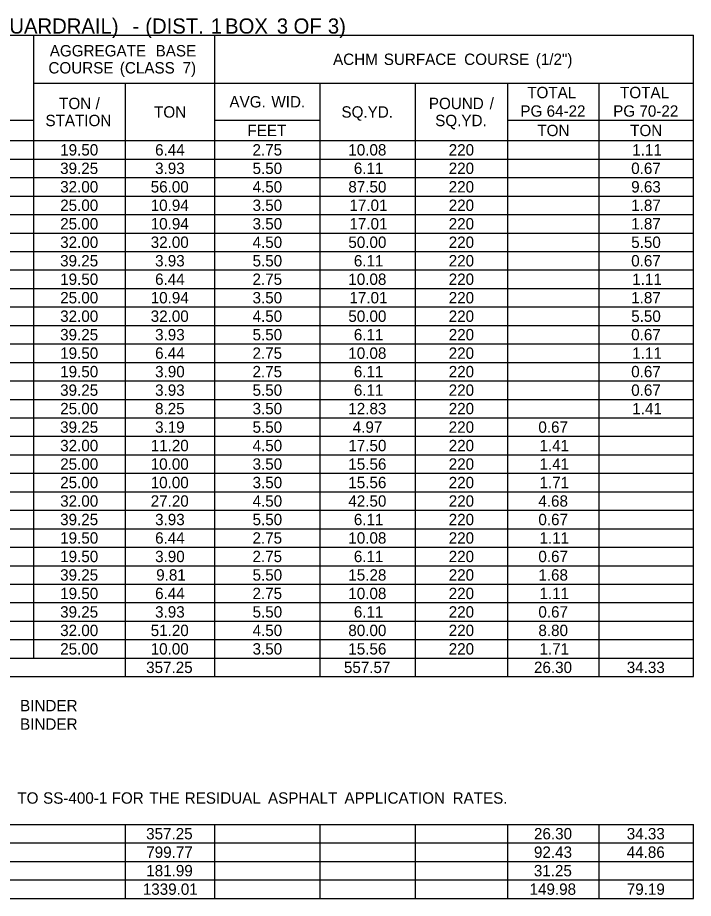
# Model space of a CAD drawing. Extents: x 542596 to 1930787, y -1948294 to 596640.
# Drawn here: x 554490.8 to 554847.5, y -1946673.7 to -1946209.1 of the extents above; entities that cross this region are included whole.
import ezdxf

# ---------------------------------------------------------------- set-up
doc = ezdxf.new("R2010")
doc.units = 0
doc.layers.add('Default', color=7, linetype='Continuous')

msp = doc.modelspace()

# ---------------------------------------------------------------- linework, layer by layer
at = {"layer": 'Default'}
for p, q in [((554098.71, -1946218.4), (554847.51, -1946218.4)), ((554499.43, -1946546.98), (554499.43, -1946218.4)), ((554594.98, -1946556.73), (554594.98, -1946218.4)), ((554847.51, -1946556.73), (554847.51, -1946218.4)), ((554499.43, -1946243.75), (554847.51, -1946243.75)), ((554547.7, -1946556.73), (554547.7, -1946243.75)), ((554650.56, -1946243.75), (554700.77, -1946243.75)), ((554650.56, -1946556.73), (554650.56, -1946243.75)), ((554700.77, -1946556.73), (554700.77, -1946243.75)), ((554749.52, -1946556.73), (554749.52, -1946243.75)), ((554797.78, -1946556.73), (554797.78, -1946243.75)), ((554452.15, -1946263.25), (554499.43, -1946263.25)), ((554499.43, -1946546.98), (554499.43, -1946263.25)), ((554594.98, -1946263.25), (554650.56, -1946263.25)), ((554594.98, -1946273.98), (554594.98, -1946263.25)), ((554650.56, -1946303.23), (554650.56, -1946263.25)), ((554749.52, -1946263.25), (554847.51, -1946263.25)), ((554098.71, -1946273.98), (554847.51, -1946273.98)), ((554499.43, -1946273.98), (554650.56, -1946273.98)), ((554547.7, -1946303.23), (554547.7, -1946273.98)), ((554650.56, -1946273.98), (554847.51, -1946273.98)), ((554700.77, -1946303.23), (554700.77, -1946273.98)), ((554329.78, -1946283.73), (554847.51, -1946283.73)), ((554329.78, -1946293.48), (554847.51, -1946293.48)), ((554329.78, -1946303.23), (554847.51, -1946303.23)), ((554329.78, -1946312.98), (554797.78, -1946312.98)), ((554547.7, -1946556.73), (554547.7, -1946312.98)), ((554650.56, -1946439.73), (554650.56, -1946312.98)), ((554749.52, -1946312.98), (554797.78, -1946312.98)), ((554797.78, -1946312.98), (554847.51, -1946312.98)), ((554329.78, -1946322.73), (554847.51, -1946322.73)), ((554329.78, -1946332.48), (554847.51, -1946332.48)), ((554329.78, -1946342.23), (554847.51, -1946342.23)), ((554329.78, -1946351.98), (554847.51, -1946351.98)), ((554700.77, -1946546.98), (554700.77, -1946351.98)), ((554329.78, -1946361.73), (554847.51, -1946361.73)), ((554329.78, -1946371.48), (554847.51, -1946371.48)), ((554329.78, -1946381.23), (554847.51, -1946381.23)), ((554329.78, -1946390.98), (554847.51, -1946390.98)), ((554329.78, -1946400.73), (554847.51, -1946400.73)), ((554329.78, -1946410.48), (554847.51, -1946410.48)), ((554329.78, -1946420.23), (554847.51, -1946420.23)), ((554329.78, -1946429.98), (554847.51, -1946429.98)), ((554329.78, -1946439.73), (554847.51, -1946439.73)), ((554329.78, -1946449.48), (554847.51, -1946449.48)), ((554650.56, -1946556.73), (554650.56, -1946449.48)), ((554329.78, -1946459.23), (554847.51, -1946459.23)), ((554329.78, -1946468.98), (554847.51, -1946468.98)), ((554329.78, -1946478.73), (554847.51, -1946478.73)), ((554270.31, -1946488.48), (554847.51, -1946488.48)), ((554329.78, -1946498.23), (554847.51, -1946498.23)), ((554329.78, -1946507.98), (554847.51, -1946507.98)), ((554329.78, -1946517.73), (554847.51, -1946517.73)), ((554329.78, -1946527.48), (554847.51, -1946527.48)), ((554329.78, -1946537.23), (554847.51, -1946537.23)), ((554098.71, -1946546.98), (554847.51, -1946546.98)), ((554547.7, -1946546.98), (554594.98, -1946546.98)), ((554594.98, -1946546.98), (554650.56, -1946546.98)), ((554594.98, -1946556.73), (554594.98, -1946546.98)), ((554650.56, -1946546.98), (554700.77, -1946546.98)), ((554700.77, -1946546.98), (554847.51, -1946546.98)), ((554749.52, -1946556.73), (554749.52, -1946546.98)), ((554329.78, -1946556.73), (554847.51, -1946556.73)), ((554329.78, -1946634.73), (554847.51, -1946634.73)), ((554329.78, -1946634.73), (554847.51, -1946634.73)), ((554547.7, -1946673.73), (554547.7, -1946634.73)), ((554594.98, -1946673.73), (554594.98, -1946634.73)), ((554594.98, -1946673.73), (554594.98, -1946634.73)), ((554650.56, -1946673.73), (554650.56, -1946634.73)), ((554650.56, -1946673.73), (554650.56, -1946634.73)), ((554700.77, -1946673.73), (554700.77, -1946634.73)), ((554700.77, -1946673.73), (554700.77, -1946634.73)), ((554749.52, -1946673.73), (554749.52, -1946634.73)), ((554749.52, -1946673.73), (554749.52, -1946634.73)), ((554797.78, -1946673.73), (554797.78, -1946634.73)), ((554847.51, -1946673.73), (554847.51, -1946634.73)), ((554329.78, -1946644.48), (554847.51, -1946644.48)), ((554329.78, -1946654.23), (554847.51, -1946654.23)), ((554329.78, -1946663.98), (554847.51, -1946663.98)), ((554329.78, -1946673.73), (554847.51, -1946673.73))]:
    msp.add_line(p, q, dxfattribs=at)

# ---------------------------------------------------------------- texts
for s, height, p in [(' GUARDRAIL)', 8, (554475.15, -1946217.53)), (' (DIST.', 8, (554555.21, -1946217.53)), (' 1', 8, (554589.83, -1946217.53)), (' BOX', 8, (554597.34, -1946217.53)), (' 3', 8, (554624.65, -1946217.53)), (' OF', 8, (554633.49, -1946217.53)), (' 3)', 8, (554651.6, -1946217.53)), (' -', 8, (554548.47, -1946217.53)), ('AGGREGATE', 6, (554507.79, -1946229.58)), (' BASE', 6, (554561.42, -1946229.58)), ('ACHM', 6, (554657.31, -1946234.08)), (' SURFACE', 6, (554681.86, -1946234.08)), (' COURSE', 6, (554724.3, -1946234.08)), (' (1/2")', 6, (554762.08, -1946234.08)), ('COURSE', 6, (554507.08, -1946238.58)), (' (CLASS', 6, (554542.54, -1946238.58)), (' 7)', 6, (554575.66, -1946238.58)), ('TOTAL', 6, (554759.81, -1946251.63)), ('TOTAL', 6, (554808.8, -1946251.63)), ('TON', 6, (554512.72, -1946257.37)), (' /', 6, (554529.75, -1946257.37)), ('AVG.', 6, (554602.62, -1946256.5)), (' WID.', 6, (554622.54, -1946256.5)), ('POUND', 6, (554707.88, -1946257.37)), (' /', 6, (554737.75, -1946257.37)), ('TON', 6, (554562.83, -1946261.87)), ('SQ.YD.', 6, (554661.74, -1946261.87)), ('PG', 6, (554756.18, -1946261.38)), (' 64-22', 6, (554767.79, -1946261.38)), ('PG', 6, (554805.17, -1946261.38)), (' 70-22', 6, (554816.78, -1946261.38)), ('STATION', 6, (554505.5, -1946266.37)), ('SQ.YD.', 6, (554711.23, -1946266.37)), ('FEET', 6, (554612.14, -1946271.62)), ('TON', 6, (554765.14, -1946271.62)), ('TON', 6, (554814.13, -1946271.62)), ('19.50', 6, (554513.28, -1946281.85)), ('6.44', 6, (554563.39, -1946281.85)), ('2.75', 6, (554614.78, -1946281.85)), ('10.08', 6, (554665.37, -1946281.85)), ('220', 6, (554718.36, -1946281.85)), ('1.11', 6, (554815.26, -1946281.85)), ('39.25', 6, (554513.25, -1946291.6)), ('3.93', 6, (554563.38, -1946291.6)), ('5.50', 6, (554614.82, -1946291.6)), ('6.11', 6, (554668.28, -1946291.6)), ('220', 6, (554718.36, -1946291.6)), ('0.67', 6, (554814.68, -1946291.6)), ('32.00', 6, (554513.28, -1946301.35)), ('56.00', 6, (554561.06, -1946301.35)), ('4.50', 6, (554614.82, -1946301.35)), ('87.50', 6, (554665.38, -1946301.35)), ('220', 6, (554718.36, -1946301.35)), ('9.63', 6, (554814.68, -1946301.35)), ('25.00', 6, (554513.28, -1946311.1)), ('10.94', 6, (554561.06, -1946311.1)), ('3.50', 6, (554614.82, -1946311.1)), ('17.01', 6, (554665.95, -1946311.1)), ('220', 6, (554718.36, -1946311.1)), ('1.87', 6, (554814.68, -1946311.1)), ('25.00', 6, (554513.28, -1946320.85)), ('10.94', 6, (554561.06, -1946320.85)), ('3.50', 6, (554614.82, -1946320.85)), ('17.01', 6, (554665.95, -1946320.85)), ('220', 6, (554718.36, -1946320.85)), ('1.87', 6, (554814.68, -1946320.85)), ('32.00', 6, (554513.28, -1946330.6)), ('32.00', 6, (554561.06, -1946330.6)), ('4.50', 6, (554614.82, -1946330.6)), ('50.00', 6, (554665.38, -1946330.6)), ('220', 6, (554718.36, -1946330.6)), ('5.50', 6, (554814.69, -1946330.6)), ('39.25', 6, (554513.25, -1946340.35)), ('3.93', 6, (554563.38, -1946340.35)), ('5.50', 6, (554614.82, -1946340.35)), ('6.11', 6, (554668.28, -1946340.35)), ('220', 6, (554718.36, -1946340.35)), ('0.67', 6, (554814.68, -1946340.35)), ('19.50', 6, (554513.28, -1946350.1)), ('6.44', 6, (554563.39, -1946350.1)), ('2.75', 6, (554614.78, -1946350.1)), ('10.08', 6, (554665.37, -1946350.1)), ('220', 6, (554718.36, -1946350.1)), ('1.11', 6, (554815.26, -1946350.1)), ('25.00', 6, (554513.28, -1946359.85)), ('10.94', 6, (554561.06, -1946359.85)), ('3.50', 6, (554614.82, -1946359.85)), ('17.01', 6, (554665.95, -1946359.85)), ('220', 6, (554718.36, -1946359.85)), ('1.87', 6, (554814.68, -1946359.85)), ('32.00', 6, (554513.28, -1946369.6)), ('32.00', 6, (554561.06, -1946369.6)), ('4.50', 6, (554614.82, -1946369.6)), ('50.00', 6, (554665.38, -1946369.6)), ('220', 6, (554718.36, -1946369.6)), ('5.50', 6, (554814.69, -1946369.6)), ('39.25', 6, (554513.25, -1946379.35)), ('3.93', 6, (554563.38, -1946379.35)), ('5.50', 6, (554614.82, -1946379.35)), ('6.11', 6, (554668.28, -1946379.35)), ('220', 6, (554718.36, -1946379.35)), ('0.67', 6, (554814.68, -1946379.35)), ('19.50', 6, (554513.28, -1946389.1)), ('6.44', 6, (554563.39, -1946389.1)), ('2.75', 6, (554614.78, -1946389.1)), ('10.08', 6, (554665.37, -1946389.1)), ('220', 6, (554718.36, -1946389.1)), ('1.11', 6, (554815.26, -1946389.1)), ('19.50', 6, (554513.28, -1946398.85)), ('3.90', 6, (554563.39, -1946398.85)), ('2.75', 6, (554614.78, -1946398.85)), ('6.11', 6, (554668.28, -1946398.85)), ('220', 6, (554718.36, -1946398.85)), ('0.67', 6, (554814.68, -1946398.85)), ('39.25', 6, (554513.25, -1946408.6)), ('3.93', 6, (554563.38, -1946408.6)), ('5.50', 6, (554614.82, -1946408.6)), ('6.11', 6, (554668.28, -1946408.6)), ('220', 6, (554718.36, -1946408.6)), ('0.67', 6, (554814.68, -1946408.6)), ('25.00', 6, (554513.28, -1946418.35)), ('8.25', 6, (554563.35, -1946418.35)), ('3.50', 6, (554614.82, -1946418.35)), ('12.83', 6, (554665.37, -1946418.35)), ('220', 6, (554718.36, -1946418.35)), ('1.41', 6, (554815.26, -1946418.35)), ('39.25', 6, (554513.25, -1946428.1)), ('3.19', 6, (554563.37, -1946428.1)), ('5.50', 6, (554614.82, -1946428.1)), ('4.97', 6, (554667.7, -1946428.1)), ('220', 6, (554718.36, -1946428.1)), ('0.67', 6, (554765.69, -1946428.1)), ('32.00', 6, (554513.28, -1946437.85)), ('11.20', 6, (554561.06, -1946437.85)), ('4.50', 6, (554614.82, -1946437.85)), ('17.50', 6, (554665.38, -1946437.85)), ('220', 6, (554718.36, -1946437.85)), ('1.41', 6, (554766.27, -1946437.85)), ('25.00', 6, (554513.28, -1946447.6)), ('10.00', 6, (554561.06, -1946447.6)), ('3.50', 6, (554614.82, -1946447.6)), ('15.56', 6, (554665.37, -1946447.6)), ('220', 6, (554718.36, -1946447.6)), ('1.41', 6, (554766.27, -1946447.6)), ('25.00', 6, (554513.28, -1946457.35)), ('10.00', 6, (554561.06, -1946457.35)), ('3.50', 6, (554614.82, -1946457.35)), ('15.56', 6, (554665.37, -1946457.35)), ('220', 6, (554718.36, -1946457.35)), ('1.71', 6, (554766.27, -1946457.35)), ('32.00', 6, (554513.28, -1946467.1)), ('27.20', 6, (554561.06, -1946467.1)), ('4.50', 6, (554614.82, -1946467.1)), ('42.50', 6, (554665.38, -1946467.1)), ('220', 6, (554718.36, -1946467.1)), ('4.68', 6, (554765.68, -1946467.1)), ('39.25', 6, (554513.25, -1946476.85)), ('3.93', 6, (554563.38, -1946476.85)), ('5.50', 6, (554614.82, -1946476.85)), ('6.11', 6, (554668.28, -1946476.85)), ('220', 6, (554718.36, -1946476.85)), ('0.67', 6, (554765.69, -1946476.85)), ('19.50', 6, (554513.28, -1946486.6)), ('6.44', 6, (554563.39, -1946486.6)), ('2.75', 6, (554614.78, -1946486.6)), ('10.08', 6, (554665.37, -1946486.6)), ('220', 6, (554718.36, -1946486.6)), ('1.11', 6, (554766.27, -1946486.6)), ('19.50', 6, (554513.28, -1946496.35)), ('3.90', 6, (554563.39, -1946496.35)), ('2.75', 6, (554614.78, -1946496.35)), ('6.11', 6, (554668.28, -1946496.35)), ('220', 6, (554718.36, -1946496.35)), ('0.67', 6, (554765.69, -1946496.35)), ('39.25', 6, (554513.25, -1946506.1)), ('9.81', 6, (554563.96, -1946506.1)), ('5.50', 6, (554614.82, -1946506.1)), ('15.28', 6, (554665.37, -1946506.1)), ('220', 6, (554718.36, -1946506.1)), ('1.68', 6, (554765.68, -1946506.1)), ('19.50', 6, (554513.28, -1946515.85)), ('6.44', 6, (554563.39, -1946515.85)), ('2.75', 6, (554614.78, -1946515.85)), ('10.08', 6, (554665.37, -1946515.85)), ('220', 6, (554718.36, -1946515.85)), ('1.11', 6, (554766.27, -1946515.85)), ('39.25', 6, (554513.25, -1946525.6)), ('3.93', 6, (554563.38, -1946525.6)), ('5.50', 6, (554614.82, -1946525.6)), ('6.11', 6, (554668.28, -1946525.6)), ('220', 6, (554718.36, -1946525.6)), ('0.67', 6, (554765.69, -1946525.6)), ('32.00', 6, (554513.28, -1946535.35)), ('51.20', 6, (554561.06, -1946535.35)), ('4.50', 6, (554614.82, -1946535.35)), ('80.00', 6, (554665.38, -1946535.35)), ('220', 6, (554718.36, -1946535.35)), ('8.80', 6, (554765.7, -1946535.35)), ('25.00', 6, (554513.28, -1946545.1)), ('10.00', 6, (554561.06, -1946545.1)), ('3.50', 6, (554614.82, -1946545.1)), ('15.56', 6, (554665.37, -1946545.1)), ('220', 6, (554718.36, -1946545.1)), ('1.71', 6, (554766.27, -1946545.1)), ('357.25', 6, (554558.65, -1946554.85)), ('557.57', 6, (554663.04, -1946554.85)), ('26.30', 6, (554763.37, -1946554.85)), ('34.33', 6, (554812.34, -1946554.85)), (' BINDER', 6, (554489.89, -1946575.03)), (' BINDER', 6, (554489.89, -1946584.78)), (' TO', 6, (554488.43, -1946623.78)), (' SS-400-1', 6, (554502.02, -1946623.78)), (' FOR', 6, (554538.21, -1946623.78)), (' THE', 6, (554558.13, -1946623.78)), (' RESIDUAL', 6, (554576.78, -1946623.78)), (' ASPHALT', 6, (554620.74, -1946623.78)), (' APPLICATION', 6, (554661.1, -1946623.78)), (' RATES.', 6, (554718.19, -1946623.78)), ('357.25', 6, (554558.65, -1946642.6)), ('26.30', 6, (554763.37, -1946642.6)), ('34.33', 6, (554812.34, -1946642.6)), ('799.77', 6, (554558.71, -1946652.35)), ('92.43', 6, (554763.35, -1946652.35)), ('44.86', 6, (554812.31, -1946652.35)), ('181.99', 6, (554558.72, -1946662.1)), ('31.25', 6, (554763.29, -1946662.1)), ('1339.01', 6, (554556.88, -1946671.85)), ('149.98', 6, (554761.03, -1946671.85)), ('79.19', 6, (554812.36, -1946671.85))]:
    msp.add_text(s, height=height, dxfattribs=at).set_placement(p)

doc.saveas('drawing.dxf')
